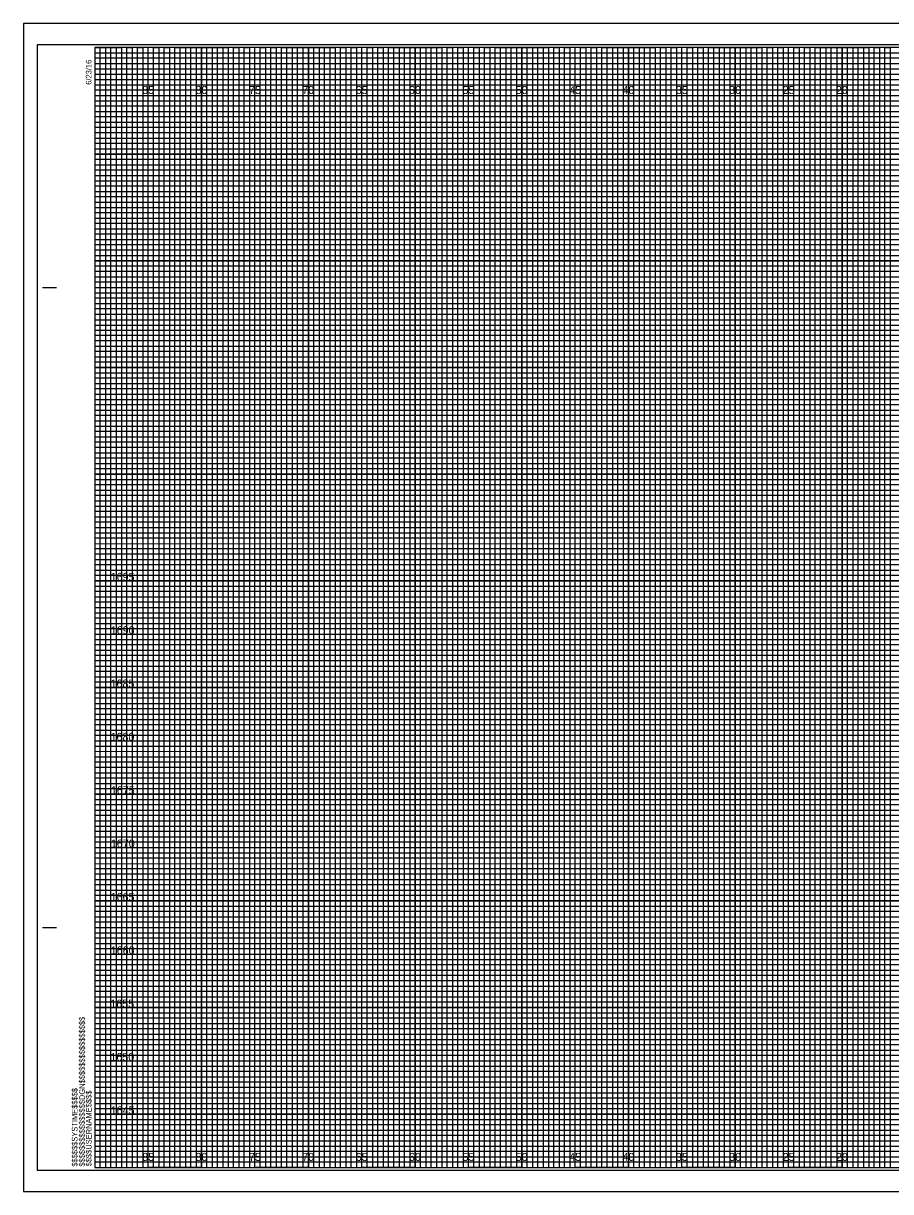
# Model space of a CAD drawing. Extents: x 172 to 723, y -2 to 439.
# Drawn here: x 541.5 to 622.8, y -0.7 to 108.8 of the extents above; entities that cross this region are included whole.
import ezdxf

# ---------------------------------------------------------------- set-up
doc = ezdxf.new("R2010")
doc.units = 0
for name, color, linetype in [('Prop XS Elevation Labels', 7, 'Continuous'), ('Prop XS Offset Labels', 7, 'Continuous'), ('Sheet Cross Section CELL', 7, 'Continuous'), ('Sheet Cross Section Grid Major CELL', 7, 'Continuous'), ('Sheet Cross Section Grid Middle CELL', 7, 'Continuous'), ('Sheet Cross Section Grid Minor 1 CELL', 7, 'Continuous'), ('Sheet Cross Section Grid Minor 2 CELL', 7, 'Continuous'), ('Sheet Cutting Line CELL', 7, 'Continuous'), ('Sheet DOT Grid CELL', 7, 'Continuous'), ('Sheet Plot Border Inside CELL', 7, 'Continuous'), ('Sheet Plot Border Outside CELL', 7, 'Continuous')]:
    doc.layers.add(name, color=color, linetype=linetype)

msp = doc.modelspace()

# ---------------------------------------------------------------- linework, layer by layer
at = {"layer": 'Sheet Cross Section CELL'}
for p, q in [((543.31, 84.07), (544.56, 84.07)), ((543.36, 84.07), (544.61, 84.07)), ((543.31, 24.07), (544.56, 24.07)), ((543.36, 24.07), (544.61, 24.07)), ((548.21, 1.57), (548.21, 1.57)), ((548.21, 1.57), (548.21, 1.57)), ((548.21, 1.57), (548.21, 1.57)), ((548.21, 1.57), (548.21, 1.57)), ((548.21, 1.57), (548.21, 1.57)), ((548.21, 1.57), (548.21, 1.57)), ((548.21, 1.57), (548.21, 1.57))]:
    msp.add_line(p, q, dxfattribs=at)
msp.add_lwpolyline([(708.21, 106.57), (548.21, 106.57), (548.21, 1.57), (708.21, 1.57)], close=True, dxfattribs=at)
at = {"layer": 'Sheet Cross Section Grid Major CELL'}
for p, q in [((553.21, 106.57), (548.21, 106.57)), ((553.21, 1.57), (553.21, 106.57)), ((563.21, 106.57), (558.21, 106.57)), ((558.21, 106.57), (558.21, 1.57)), ((563.21, 1.57), (563.21, 106.57)), ((573.21, 106.57), (568.21, 106.57)), ((568.21, 106.57), (568.21, 1.57)), ((573.21, 1.57), (573.21, 106.57)), ((583.21, 106.57), (578.21, 106.57)), ((578.21, 106.57), (578.21, 1.57)), ((583.21, 1.57), (583.21, 106.57)), ((593.21, 106.57), (588.21, 106.57)), ((588.21, 106.57), (588.21, 1.57)), ((593.21, 1.57), (593.21, 106.57)), ((603.21, 106.57), (598.21, 106.57)), ((598.21, 106.57), (598.21, 1.57)), ((603.21, 1.57), (603.21, 106.57)), ((613.21, 106.57), (608.21, 106.57)), ((608.21, 106.57), (608.21, 1.57)), ((613.21, 1.57), (613.21, 106.57)), ((623.21, 106.57), (618.21, 106.57)), ((618.21, 106.57), (618.21, 1.57)), ((558.21, 1.57), (553.21, 1.57)), ((568.21, 1.57), (563.21, 1.57)), ((578.21, 1.57), (573.21, 1.57)), ((588.21, 1.57), (583.21, 1.57)), ((598.21, 1.57), (593.21, 1.57)), ((608.21, 1.57), (603.21, 1.57)), ((618.21, 1.57), (613.21, 1.57))]:
    msp.add_line(p, q, dxfattribs=at)
for points in [[(548.21, 101.57), (708.21, 101.57), (708.21, 96.57), (548.21, 96.57)], [(548.21, 91.57), (708.21, 91.57), (708.21, 86.57), (548.21, 86.57)], [(548.21, 81.57), (708.21, 81.57), (708.21, 76.57), (548.21, 76.57)], [(548.21, 71.57), (708.21, 71.57), (708.21, 66.57), (548.21, 66.57)], [(548.21, 61.57), (708.21, 61.57), (708.21, 56.57), (548.21, 56.57)], [(548.21, 51.57), (708.21, 51.57), (708.21, 46.57), (548.21, 46.57)], [(548.21, 41.57), (708.21, 41.57), (708.21, 36.57), (548.21, 36.57)], [(548.21, 31.57), (708.21, 31.57), (708.21, 26.57), (548.21, 26.57)], [(548.21, 21.57), (708.21, 21.57), (708.21, 16.57), (548.21, 16.57)], [(548.21, 11.57), (708.21, 11.57), (708.21, 6.57), (548.21, 6.57)]]:
    msp.add_lwpolyline(points, dxfattribs=at)
at = {"layer": 'Sheet Cross Section Grid Middle CELL'}
for points in [[(548.21, 106.57), (550.71, 106.57), (550.71, 1.57), (555.71, 1.57), (555.71, 106.57), (560.71, 106.57), (560.71, 1.57), (565.71, 1.57), (565.71, 106.57), (570.71, 106.57), (570.71, 1.57), (575.71, 1.57), (575.71, 106.57), (580.71, 106.57), (580.71, 1.57), (585.71, 1.57), (585.71, 106.57), (590.71, 106.57), (590.71, 1.57), (595.71, 1.57), (595.71, 106.57), (600.71, 106.57), (600.71, 1.57), (605.71, 1.57), (605.71, 106.57), (610.71, 106.57), (610.71, 1.57), (615.71, 1.57), (615.71, 106.57), (620.71, 106.57), (620.71, 1.57), (625.71, 1.57)], [(548.21, 104.07), (685.71, 104.07)], [(548.21, 94.07), (708.21, 94.07), (708.21, 99.07), (548.21, 99.07)], [(548.21, 84.07), (708.21, 84.07), (708.21, 89.07), (548.21, 89.07)], [(548.21, 74.07), (708.21, 74.07), (708.21, 79.07), (548.21, 79.07)], [(548.21, 64.07), (708.21, 64.07), (708.21, 69.07), (548.21, 69.07)], [(548.21, 54.07), (708.21, 54.07), (708.21, 59.07), (548.21, 59.07)], [(548.21, 44.07), (708.21, 44.07), (708.21, 49.07), (548.21, 49.07)], [(548.21, 34.07), (708.21, 34.07), (708.21, 39.07), (548.21, 39.07)], [(548.21, 24.07), (708.21, 24.07), (708.21, 29.07), (548.21, 29.07)], [(548.21, 14.07), (708.21, 14.07), (708.21, 19.07), (548.21, 19.07)], [(548.21, 4.07), (708.21, 4.07), (708.21, 9.07), (548.21, 9.07)]]:
    msp.add_lwpolyline(points, dxfattribs=at)
at = {"layer": 'Sheet Cross Section Grid Minor 1 CELL'}
for p, q in [((548.21, 106.07), (678.21, 106.07)), ((678.21, 105.56), (548.21, 105.56)), ((548.21, 105.56), (548.21, 105.07)), ((548.21, 105.07), (678.21, 105.07)), ((678.21, 104.52), (548.21, 104.52)), ((548.21, 104.52), (548.21, 103.57)), ((548.21, 103.57), (708.21, 103.57))]:
    msp.add_line(p, q, dxfattribs=at)
for points in [[(548.21, 103.07), (683.21, 103.07), (708.21, 103.07), (708.21, 102.57), (548.21, 102.57)], [(548.21, 102.07), (708.21, 102.07), (708.21, 101.07), (548.21, 101.07)], [(548.21, 100.57), (708.21, 100.57), (708.21, 100.07), (548.21, 100.06)], [(548.21, 99.57), (708.21, 99.57), (708.21, 98.57), (548.21, 98.57)], [(548.21, 98.07), (708.21, 98.07), (708.21, 97.57), (548.21, 97.57)], [(548.21, 97.07), (708.21, 97.07), (708.21, 96.07), (548.21, 96.07)], [(548.21, 95.57), (708.21, 95.57), (708.21, 95.07), (548.21, 95.07)], [(548.21, 94.57), (708.21, 94.57), (708.21, 93.57), (548.21, 93.57)], [(548.21, 93.07), (708.21, 93.07), (708.21, 92.57), (548.21, 92.57)], [(548.21, 92.07), (708.21, 92.07), (708.21, 91.07), (548.21, 91.07)], [(548.21, 90.57), (708.21, 90.57), (708.21, 90.07), (548.21, 90.07)], [(548.21, 89.57), (708.21, 89.57), (708.21, 88.55), (708.21, 88.07), (708.21, 87.57), (548.21, 87.57)], [(548.21, 88.57), (708.21, 88.57), (708.21, 88.07), (548.21, 88.07)], [(548.21, 87.07), (708.21, 87.07), (708.21, 86.07), (548.21, 86.09)], [(548.21, 86.09), (708.21, 86.07), (708.21, 85.57), (548.21, 85.57)], [(548.21, 85.07), (708.21, 85.07), (708.21, 84.57), (548.21, 84.57)], [(548.21, 83.57), (708.21, 83.57), (708.21, 83.07), (548.21, 83.07)], [(548.21, 82.57), (708.21, 82.57), (708.21, 82.07), (548.21, 82.07)], [(548.18, 81.02), (708.21, 81.02), (708.21, 80.51), (548.18, 80.51)], [(548.21, 80.07), (708.21, 80.07), (708.21, 79.57), (548.21, 79.57)], [(548.21, 78.57), (708.21, 78.57), (708.21, 78.07), (548.21, 78.07)], [(548.21, 77.57), (708.21, 77.57), (708.21, 77.07), (548.21, 77.07)], [(548.21, 76.07), (708.21, 76.07), (708.21, 75.57), (548.21, 75.57)], [(548.21, 75.07), (708.21, 75.07), (708.21, 74.57), (548.21, 74.57)], [(548.21, 73.57), (708.21, 73.57), (708.21, 73.07), (548.21, 73.07)], [(548.21, 72.57), (708.21, 72.57), (708.21, 72.07), (548.21, 72.07)], [(548.21, 71.07), (708.21, 71.07), (708.21, 70.56), (548.21, 70.57)], [(548.21, 70.07), (708.21, 70.07), (708.21, 69.57), (548.21, 69.57)], [(548.21, 68.57), (708.21, 68.57), (708.21, 68.07), (548.21, 68.07)], [(548.21, 67.57), (708.21, 67.57), (708.21, 67.07), (548.21, 67.07)], [(548.21, 66.07), (708.21, 66.07), (708.21, 65.57), (548.21, 65.57)], [(548.21, 65.07), (708.21, 65.07), (708.21, 64.57), (548.21, 64.57)], [(548.21, 63.57), (708.21, 63.57), (708.21, 63.07), (548.21, 63.07)], [(548.21, 62.57), (708.21, 62.57), (708.21, 62.07), (548.21, 62.07)], [(548.21, 61.07), (708.21, 61.07), (708.21, 60.57), (548.21, 60.57)], [(548.21, 60.07), (708.25, 60.03), (708.21, 59.57), (548.21, 59.57)], [(548.21, 58.57), (708.21, 58.57), (708.21, 58.07), (548.21, 58.07)], [(548.21, 57.57), (708.21, 57.57), (708.21, 57.07), (548.21, 57.07)], [(548.21, 56.07), (708.21, 56.07), (708.21, 55.57), (548.21, 55.57)], [(548.21, 55.07), (708.21, 55.07), (708.21, 54.57), (548.21, 54.57)], [(548.21, 53.57), (708.21, 53.57), (708.21, 53.07), (548.21, 53.07)], [(548.21, 52.57), (708.21, 52.57), (708.21, 52.07), (548.21, 52.07)], [(548.21, 51.07), (708.21, 51.07), (708.21, 50.57), (548.21, 50.57)], [(548.21, 50.07), (708.21, 50.07), (708.21, 49.57), (548.21, 49.57)], [(548.21, 48.57), (708.21, 48.57), (708.21, 48.07), (548.21, 48.07)], [(548.21, 47.57), (708.21, 47.57), (708.21, 47.07), (548.21, 47.07)], [(548.21, 46.07), (708.21, 46.07), (708.21, 45.57), (548.21, 45.57)], [(548.21, 45.07), (708.21, 45.07), (708.21, 44.57), (548.21, 44.57)], [(548.21, 43.57), (708.21, 43.57), (708.21, 43.07), (548.21, 43.07)], [(548.21, 42.57), (708.21, 42.57), (708.21, 42.07), (548.21, 42.07)], [(548.21, 41.07), (708.21, 41.07), (708.21, 40.56), (548.21, 40.57)], [(548.21, 40.07), (708.21, 40.07), (708.21, 39.57), (548.21, 39.57)], [(548.21, 38.57), (708.21, 38.57), (708.21, 38.07), (548.21, 38.07)], [(548.21, 37.57), (708.21, 37.57), (708.21, 37.07), (548.21, 37.07)], [(548.21, 36.07), (708.21, 36.07), (708.21, 35.57), (548.21, 35.57)], [(548.21, 35.07), (708.21, 35.07), (708.21, 34.57), (548.21, 34.57)], [(548.21, 33.57), (708.21, 33.57), (708.21, 33.07), (548.21, 33.07)], [(548.21, 32.57), (708.21, 32.57), (708.21, 32.07), (548.21, 32.07)], [(548.21, 31.07), (708.21, 31.07), (708.21, 30.57), (548.21, 30.57)], [(548.21, 30.07), (708.25, 30.03), (708.21, 29.57), (548.21, 29.57)], [(548.21, 28.57), (708.21, 28.57), (708.21, 28.07), (548.21, 28.07)], [(548.21, 27.57), (708.21, 27.57), (708.21, 27.07), (548.21, 27.07)], [(548.21, 26.07), (708.21, 26.07), (708.21, 25.57), (548.21, 25.57)], [(548.21, 25.07), (708.21, 25.07), (708.21, 24.57), (548.21, 24.57)], [(548.21, 23.57), (708.21, 23.57), (708.21, 23.07), (548.21, 23.07)], [(548.21, 22.57), (708.21, 22.57), (708.21, 22.07), (548.21, 22.07)], [(548.21, 21.07), (708.21, 21.07), (708.21, 20.57), (548.21, 20.57)], [(548.21, 20.07), (708.21, 20.07), (708.21, 19.57), (548.21, 19.57)], [(548.21, 18.57), (708.21, 18.57), (708.21, 18.07), (548.21, 18.07)], [(548.21, 17.57), (708.21, 17.57), (708.21, 17.07), (548.21, 17.07)], [(548.21, 16.07), (708.21, 16.07), (708.21, 15.57), (548.21, 15.57)], [(548.21, 15.07), (708.21, 15.07), (708.21, 14.57), (548.21, 14.57)], [(548.21, 13.57), (708.21, 13.57), (708.21, 13.07), (548.21, 13.07)], [(548.21, 12.57), (708.21, 12.57), (708.21, 12.07), (548.21, 12.07)], [(548.21, 11.07), (708.21, 11.07), (708.21, 10.57), (548.21, 10.57)], [(548.21, 10.07), (708.21, 10.07), (708.21, 9.57), (548.21, 9.57)], [(548.21, 8.57), (708.21, 8.57), (708.21, 8.07), (548.21, 8.07)], [(548.21, 7.57), (708.21, 7.57), (708.21, 7.07), (548.21, 7.07)], [(548.21, 6.07), (708.21, 6.07), (708.21, 5.57), (548.21, 5.57)], [(548.21, 5.07), (708.21, 5.07), (708.21, 4.57), (548.21, 4.57)], [(548.21, 3.57), (708.21, 3.57), (708.21, 3.07), (548.21, 3.07)], [(548.21, 2.57), (708.21, 2.57), (708.21, 2.07), (548.21, 2.07)]]:
    msp.add_lwpolyline(points, dxfattribs=at)
at = {"layer": 'Sheet Cross Section Grid Minor 2 CELL'}
for points in [[(548.21, 1.57), (548.71, 1.57), (548.71, 106.57), (549.21, 106.57), (549.21, 1.57)], [(549.21, 1.57), (549.71, 1.57), (549.71, 106.57), (550.21, 106.57), (550.21, 1.57)], [(550.71, 1.57), (551.21, 1.57), (551.21, 106.57), (551.71, 106.57), (551.71, 1.57)], [(551.71, 1.57), (552.21, 1.57), (552.21, 106.57), (552.71, 106.57), (552.71, 1.57)], [(553.21, 1.57), (553.71, 1.57), (553.71, 106.57), (554.21, 106.57), (554.21, 1.57)], [(554.21, 1.57), (554.71, 1.57), (554.71, 106.57), (555.21, 106.57), (555.21, 1.57)], [(555.71, 1.57), (556.21, 1.57), (556.21, 106.57), (556.71, 106.57), (556.71, 1.57)], [(556.71, 1.57), (557.21, 1.57), (557.21, 106.57), (557.71, 106.57), (557.71, 1.57)], [(558.21, 1.57), (558.71, 1.57), (558.71, 106.57), (559.21, 106.57), (559.21, 1.57)], [(559.21, 1.57), (559.71, 1.57), (559.71, 106.57), (560.21, 106.57), (560.21, 1.57)], [(560.71, 1.57), (561.21, 1.57), (561.21, 106.57), (561.71, 106.57), (561.71, 1.57)], [(561.71, 1.57), (562.21, 1.57), (562.21, 106.57), (562.71, 106.57), (562.71, 1.57)], [(563.21, 1.57), (563.71, 1.57), (563.71, 106.57), (564.21, 106.57), (564.21, 1.57)], [(564.21, 1.57), (564.71, 1.57), (564.71, 106.57), (565.21, 106.57), (565.21, 1.57)], [(565.71, 1.57), (566.21, 1.57), (566.21, 106.57), (566.71, 106.57), (566.71, 1.57)], [(566.71, 1.57), (567.21, 1.57), (567.21, 106.57), (567.71, 106.57), (567.71, 1.57)], [(568.21, 1.57), (568.71, 1.57), (568.71, 106.57), (569.21, 106.57), (569.21, 1.57)], [(569.21, 1.57), (569.71, 1.57), (569.71, 106.57), (570.21, 106.57), (570.21, 1.57)], [(570.71, 1.57), (571.21, 1.57), (571.21, 106.57), (571.71, 106.57), (571.71, 1.57)], [(571.71, 1.57), (572.21, 1.57), (572.21, 106.57), (572.71, 106.57), (572.71, 1.57)], [(573.21, 1.57), (573.71, 1.57), (573.71, 106.57), (574.21, 106.57), (574.21, 1.57)], [(574.21, 1.57), (574.71, 1.57), (574.71, 106.57), (575.21, 106.57), (575.21, 1.57)], [(575.71, 1.57), (576.21, 1.57), (576.21, 106.57), (576.71, 106.57), (576.71, 1.57)], [(576.71, 1.57), (577.21, 1.57), (577.21, 106.57), (577.71, 106.57), (577.71, 1.57)], [(578.21, 1.57), (578.71, 1.57), (578.71, 106.57), (579.21, 106.57), (579.21, 1.57)], [(579.21, 1.57), (579.71, 1.57), (579.71, 106.57), (580.21, 106.57), (580.21, 1.57)], [(580.71, 1.57), (581.21, 1.57), (581.21, 106.57), (581.71, 106.57), (581.71, 1.57)], [(581.71, 1.57), (582.21, 1.57), (582.21, 106.57), (582.71, 106.57), (582.71, 1.57)], [(583.21, 1.57), (583.71, 1.57), (583.71, 106.57), (584.21, 106.57), (584.21, 1.57)], [(584.21, 1.57), (584.71, 1.57), (584.71, 106.57), (585.21, 106.57), (585.21, 1.57)], [(585.71, 1.57), (586.21, 1.57), (586.21, 106.57), (586.71, 106.57), (586.71, 1.57)], [(586.71, 1.57), (587.21, 1.57), (587.21, 106.57), (587.71, 106.57), (587.71, 1.57)], [(588.21, 1.57), (588.71, 1.57), (588.71, 106.57), (589.21, 106.57), (589.21, 1.57)], [(589.21, 1.57), (589.71, 1.57), (589.71, 106.57), (590.21, 106.57), (590.21, 1.57)], [(590.71, 1.57), (591.21, 1.57), (591.21, 106.57), (591.71, 106.57), (591.71, 1.57)], [(591.71, 1.57), (592.21, 1.57), (592.21, 106.57), (592.71, 106.57), (592.71, 1.57)], [(593.21, 1.57), (593.71, 1.57), (593.71, 106.57), (594.21, 106.57), (594.21, 1.57)], [(594.21, 1.57), (594.71, 1.57), (594.71, 106.57), (595.21, 106.57), (595.21, 1.57)], [(595.71, 1.57), (596.21, 1.57), (596.21, 106.57), (596.71, 106.57), (596.71, 1.57)], [(596.71, 1.57), (597.21, 1.57), (597.21, 106.57), (597.71, 106.57), (597.71, 1.57)], [(598.21, 1.57), (598.71, 1.57), (598.71, 106.57), (599.21, 106.57), (599.21, 1.57)], [(599.21, 1.57), (599.71, 1.57), (599.71, 106.57), (600.21, 106.57), (600.21, 1.57)], [(600.71, 1.57), (601.21, 1.57), (601.21, 106.57), (601.71, 106.57), (601.71, 1.57)], [(601.71, 1.57), (602.21, 1.57), (602.21, 106.57), (602.71, 106.57), (602.71, 1.57)], [(603.21, 1.57), (603.71, 1.57), (603.71, 106.57), (604.21, 106.57), (604.21, 1.57)], [(604.21, 1.57), (604.71, 1.57), (604.71, 106.57), (605.21, 106.57), (605.21, 1.57)], [(605.71, 1.57), (606.21, 1.57), (606.21, 106.57), (606.71, 106.57), (606.71, 1.57)], [(606.71, 1.57), (607.21, 1.57), (607.21, 106.57), (607.71, 106.57), (607.71, 1.57)], [(608.21, 1.57), (608.71, 1.57), (608.71, 106.57), (609.21, 106.57), (609.21, 1.57)], [(609.21, 1.57), (609.71, 1.57), (609.71, 106.57), (610.21, 106.57), (610.21, 1.57)], [(610.71, 1.57), (611.21, 1.57), (611.21, 106.57), (611.71, 106.57), (611.71, 1.57)], [(611.71, 1.57), (612.21, 1.57), (612.21, 106.57), (612.71, 106.57), (612.71, 1.57)], [(613.21, 1.57), (613.71, 1.57), (613.71, 106.57), (614.21, 106.57), (614.21, 1.57)], [(614.21, 1.57), (614.71, 1.57), (614.71, 106.57), (615.21, 106.57), (615.21, 1.57)], [(615.71, 1.57), (616.21, 1.57), (616.21, 106.57), (616.71, 106.57), (616.71, 1.57)], [(616.71, 1.57), (617.21, 1.57), (617.21, 106.57), (617.71, 106.57), (617.71, 1.57)], [(618.21, 1.57), (618.71, 1.57), (618.71, 106.57), (619.21, 106.57), (619.21, 1.57)], [(619.21, 1.57), (619.71, 1.57), (619.71, 106.57), (620.21, 106.57), (620.21, 1.57)], [(620.71, 1.57), (621.21, 1.57), (621.21, 106.57), (621.71, 106.57), (621.71, 1.57)], [(621.71, 1.57), (622.21, 1.57), (622.21, 106.57), (622.71, 106.57), (622.71, 1.57)]]:
    msp.add_lwpolyline(points, dxfattribs=at)
at = {"layer": 'Sheet Cutting Line CELL'}
for p, q in [((709.86, 108.82), (541.51, 108.82)), ((541.51, 108.82), (541.51, -0.68)), ((541.51, -0.68), (709.86, -0.68))]:
    msp.add_line(p, q, dxfattribs=at)
at = {"layer": 'Sheet DOT Grid CELL'}
for p, q in [((553.21, 1.57), (553.21, 106.57)), ((558.21, 1.57), (558.21, 106.57)), ((563.21, 1.57), (563.21, 106.57)), ((568.21, 1.57), (568.21, 106.57)), ((573.21, 1.57), (573.21, 106.57)), ((578.21, 1.57), (578.21, 106.57)), ((583.21, 1.57), (583.21, 106.57)), ((588.21, 1.57), (588.21, 106.57)), ((593.21, 1.57), (593.21, 106.57)), ((598.21, 1.57), (598.21, 106.57)), ((603.21, 1.57), (603.21, 106.57)), ((608.21, 1.57), (608.21, 106.57)), ((613.21, 1.57), (613.21, 106.57)), ((618.21, 1.57), (618.21, 106.57)), ((548.21, 101.57), (708.21, 101.57)), ((548.21, 96.57), (708.21, 96.57)), ((548.21, 91.57), (708.21, 91.57)), ((548.21, 86.57), (708.21, 86.57)), ((548.21, 81.57), (708.21, 81.57)), ((548.21, 76.57), (708.21, 76.57)), ((548.21, 71.57), (708.21, 71.57)), ((548.21, 66.57), (708.21, 66.57)), ((548.21, 61.57), (708.21, 61.57)), ((548.21, 56.57), (708.21, 56.57)), ((548.21, 51.57), (708.21, 51.57)), ((548.21, 46.57), (708.21, 46.57)), ((548.21, 41.57), (708.21, 41.57)), ((548.21, 36.57), (708.21, 36.57)), ((548.21, 31.57), (708.21, 31.57)), ((548.21, 26.57), (708.21, 26.57)), ((548.21, 21.57), (708.21, 21.57)), ((548.21, 16.57), (708.21, 16.57)), ((548.21, 11.57), (708.21, 11.57)), ((548.21, 6.57), (708.21, 6.57))]:
    msp.add_line(p, q, dxfattribs=at)
at = {"layer": 'Sheet Plot Border Inside CELL'}
msp.add_lwpolyline([(542.81, 1.32), (709.41, 1.32), (709.41, 106.82), (542.81, 106.82)], close=True, dxfattribs=at)
at = {"layer": 'Sheet Plot Border Outside CELL'}
msp.add_lwpolyline([(541.51, -0.68), (709.86, -0.68), (709.86, 108.82), (541.51, 108.82)], close=True, dxfattribs=at)

# ---------------------------------------------------------------- texts
at = {"layer": 'Prop XS Elevation Labels'}
for s, p in [('1695', (549.69, 56.57)), ('1690', (549.7, 51.57)), ('1685', (549.68, 46.57)), ('1680', (549.68, 41.57)), ('1675', (549.71, 36.57)), ('1670', (549.71, 31.57)), ('1665', (549.69, 26.57)), ('1660', (549.7, 21.57)), ('1655', (549.66, 16.57)), ('1650', (549.67, 11.57)), ('1645', (549.69, 6.57))]:
    msp.add_text(s, height=0.75, dxfattribs=at).set_placement(p)
at = {"layer": 'Prop XS Offset Labels'}
for s, p in [('85', (552.65, 102.2)), ('80', (557.64, 102.2)), ('75', (562.65, 102.2)), ('70', (567.64, 102.2)), ('65', (572.65, 102.2)), ('60', (577.64, 102.2)), ('55', (582.65, 102.2)), ('50', (587.64, 102.2)), ('45', (592.65, 102.2)), ('40', (597.64, 102.2)), ('35', (602.65, 102.2)), ('30', (607.64, 102.2)), ('25', (612.65, 102.2)), ('20', (617.64, 102.2)), ('85', (552.65, 2.2)), ('80', (557.64, 2.2)), ('75', (562.65, 2.2)), ('70', (567.64, 2.2)), ('65', (572.65, 2.2)), ('60', (577.64, 2.2)), ('55', (582.65, 2.2)), ('50', (587.64, 2.2)), ('45', (592.65, 2.2)), ('40', (597.64, 2.2)), ('35', (602.65, 2.2)), ('30', (607.64, 2.2)), ('25', (612.65, 2.2)), ('20', (617.64, 2.2))]:
    msp.add_text(s, height=0.75, dxfattribs=at).set_placement(p)
at = {"layer": 'Sheet Cross Section CELL'}
for s, p in [('6/23/16', (547.89, 103.07)), ('$$$$$$$$$$$$$$$$DGN$$$$$$$$$$$$$$$$', (547.27, 1.66)), ('$$$$$$SYSTIME$$$$$', (546.58, 1.66)), ('$$$$USERNAME$$$$', (547.9, 1.69))]:
    msp.add_text(s, height=0.525, rotation=90, dxfattribs=at).set_placement(p)

doc.saveas('drawing.dxf')
